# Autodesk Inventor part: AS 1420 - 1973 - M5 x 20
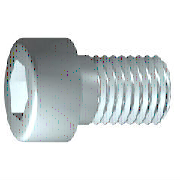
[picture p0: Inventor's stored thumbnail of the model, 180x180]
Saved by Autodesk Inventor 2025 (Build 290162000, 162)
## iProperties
Created: 2024-01
Part Number: AS 1420 - 1973 - M5 x 20
Material: Acciaio, Dolce
Description: Viti con esagono incassato metriche ISO
Document SubType Name: Modeling
Standard: AS 1420 - 1973
Designer: 18907419
Standards Organization: AS
Language: it-IT
Size Designation: M5 x 20
Categories: <MemberInstance><Categories><Category DisplayName="Elementi di fissaggio" InternalName="e4da775c-781d-43d5-af7c-5136215cf5a6" Mnemonic="FSTN"><Category DisplayN
Density: 7.85 g/cm^3
Appearance: Semilucidato
IsCustomPart: 0
Author: 18907419
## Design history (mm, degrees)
body "Solid1"
workplane "Work Plane1"
fillet "Fillet2" dims "d30" = 0.1 (= R)
revolve "Corpo" stored, may be unused: angle "d10" = 90 deg
sketch "Schizzo2"
  geometry: L1 (0, -5.95)-(0, 5.95) reference; L2 (-5.95, 0)-(5.95, 0) reference; L3 (2.309, 0)-(1.155, -2); L4 (1.155, -2)-(-1.155, -2); L5 (-1.155, -2)-(-2.309, 0); L6 (-2.309, 0)-(-1.155, 2); L7 (-1.155, 2)-(1.155, 2); L8 (1.155, 2)-(2.309, 0); 2 further points
  constraints: 12 end point, 1 coincident, 1 horizontal alignment, 1 point on line, 12 other
extrude "Intaglio" join sketch "Schizzo2" stored distance "d11" = 10; taper "d12" = 0 deg
fillet "Raccordo1" dims "d17" = 0.5 (= RR)
feature "Filettatura" dims "d13" = 16 (= GEL), "d14" = 0
chamfer "Smusso1" distance "d15" = 0.49076 (= -0.5 x SPD + 0.5 x GD); stored, may be unused: second distance "d16" = 0.49076 (= GUL), angle "d27" = 45 deg
sketch "Schizzo1"
  geometry: L1 (-1.167, 0)-(20, 0); L2 (20, 0)-(20, 2.5); L3 (20, 2.5)-(4, 2.5); L4 (4, 2.5)-(3.509, 2.5); L5 (3.509, 2.5)-(0, 2.5); L6 (0, 2.5)-(0, 4.25); L7 (0, 4.25)-(-5, 4.25); L8 (-5, 4.25)-(-5, 2.309); L9 (-5, 2.309)-(-2.5, 2.309); L10 (-2.5, 2.309)-(-1.167, 0); L11 (-10, 0)-(25, 0) reference; L12 (0, -0.85)-(0, 5.1) reference; L13 (4, 2.5)-(0, 2.5)
  constraints: 22 end point, 6 parallel, 2 collinear, 2 perpendicular, 1 horizontal, 1 point on line
  dimensions: "d1" = 16 distance from line of L3.end L2 (= GEL); "d2" = 0.49086 distance of L4.end L3.end (computed from GAL); "d3" = 5 distance between parallel lines of L8 L6 (= KOH); "d4" = 2.5 distance of L8.end L9.end (= INTI); "d5" = 60 deg angle of L10 L1; "d6" = 5 diameter of L3 L1 (= GD); "d7" = 5 diameter of L5 L1 (= BDM); "d8" = 4.6188 diameter of L9 L1 (= 1.1547 x SW); "d9" = 8.5 diameter of L7 L1 (= KOD); "d26" = 20 distance between parallel lines of L12 L2 (= NLG)
other parameters: "GD" = 5 (= NND) [user parameter; used in 2 equation terms], "NLG" = 20 [user parameter; used in 1 equation term], "GEL" = 16 [user parameter; used in 2 equation terms], "KOD" = 8.5 [user parameter; used in 1 equation term], "KOH" = 5 (= NND) [user parameter; used in 1 equation term], "INTI" = 2.5 [user parameter; used in 1 equation term], "GAL" = 0.49076 (= 0.61345 x PTC) [user parameter; used in 1 equation term], "GUL" = 0.49076 (= 0.61345 x PTC) [user parameter; used in 1 equation term], "BDM" = 5 (= NND) [user parameter; used in 1 equation term], "SW" = 4 [user parameter; used in 2 equation terms], "RR" = 0.5 (= 0.1 x NND) [user parameter; used in 1 equation term], "SPD" = 4.01848 (= NND - 1.2269 x PTC) [user parameter; used in 1 equation term], "d19" = 0, "d28" = 0, "d29" = 0, "R" = 0.1 [user parameter; used in 1 equation term], "PHH" = 0.13 [user parameter], "GD1" = 4.01848 (= THREADDIA - 1.2269 x PTC) [user parameter], "THREADDIA" = 5 [user parameter; used in 1 equation term], "FAWI" = 45 deg [user parameter], "TPU" = 12.5 (computed from PTC) [user parameter], "PTC" = 0.8 [user parameter; used in 5 equation terms], "KOH1" = 4.5 [user parameter], "NND" = 5 [user parameter; used in 5 equation terms], "TOA" = 30 deg [user parameter], "E0" = 4.62 (= 1.155 x SW) [user parameter]
